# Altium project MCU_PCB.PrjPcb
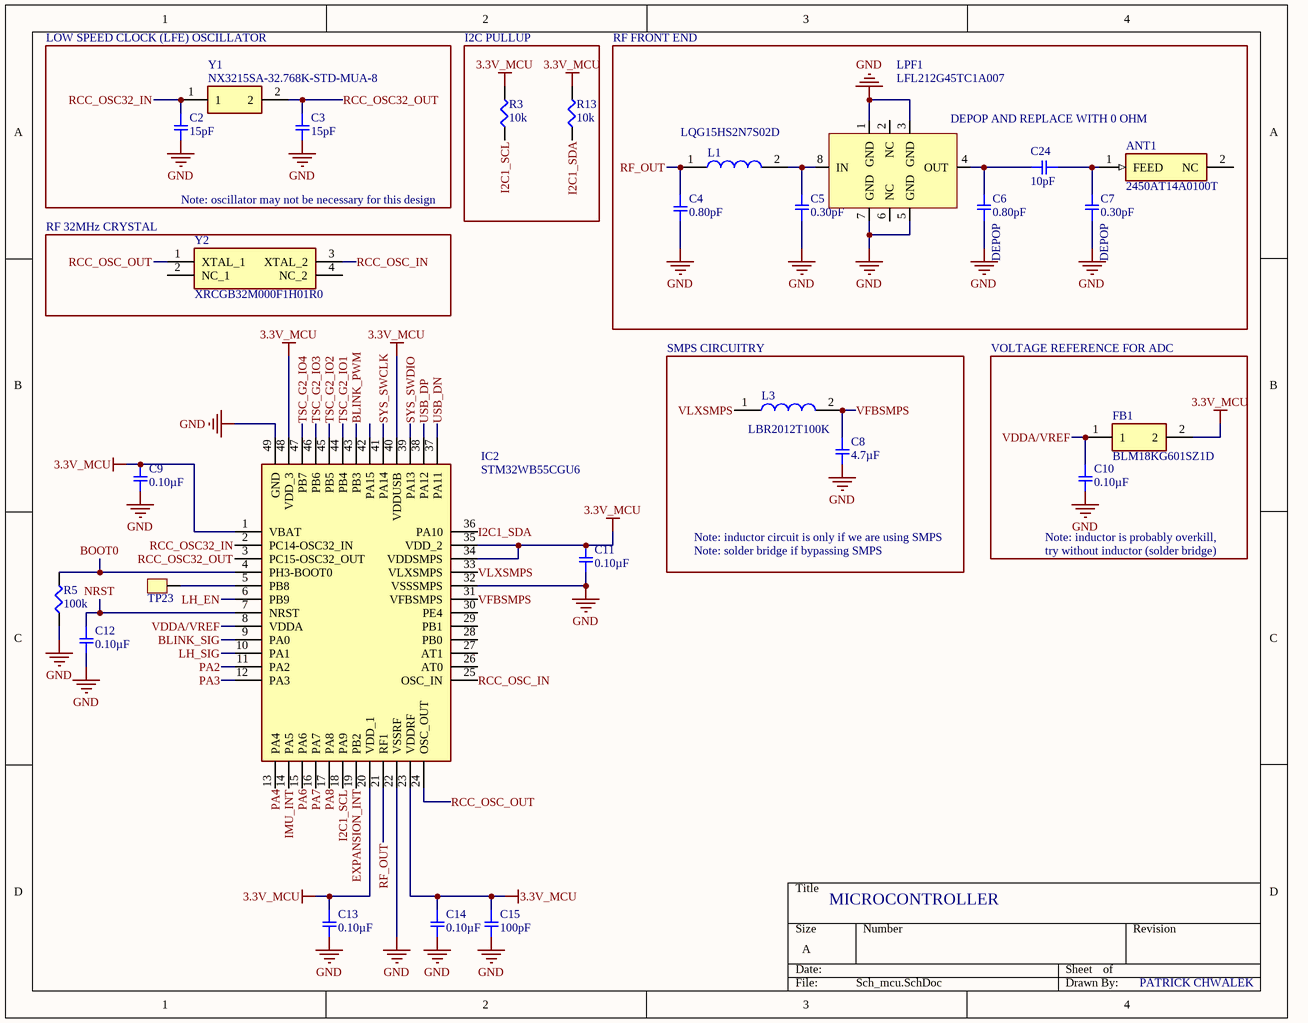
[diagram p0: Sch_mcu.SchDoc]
5 sheets, 82 parts. Net scope: global (net labels, ports and power ports of the same name join across sheets).
Board file: MCU_PCB_v2.PcbDoc
Sheets:
  Sch_mcu.SchDoc
  Sch_sensors.SchDoc
  Sch_external_connectors.SchDoc
  Sch_pwr.SchDoc
  Sch_stackup_mcu_pcb.SchDoc

## Sheet Sch_mcu.SchDoc
size A

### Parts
ANT1  2450AT14A0100T  [ANTC1608X40N]
C2  15pF  [SMD-0402C]
C3  15pF  [SMD-0402C]
C4  0.80pF  [SMD-0402C]
C5  0.30pF  [SMD-0402C]
C6  0.80pF  [SMD-0402C]
C7  0.30pF  [SMD-0402C]
C8  4.7µF  [SMD-0402C]
C9  0.10µF  [SMD-0402C]
C10  0.10µF  [SMD-0402C]
C11  0.10µF  [SMD-0402C]
C12  0.10µF  [SMD-0402C]
C13  0.10µF  [SMD-0402C]
C14  0.10µF  [SMD-0402C]
C15  100pF  [SMD-0402C]
C24  10pF  [SMD-0402C]
FB1  BLM18KG601SZ1D  [BEADC1608X95N]
IC2  STM32WB55CGU6  [QFN50P700X700X65-49N-D]
L1  LQG15HS2N7S02D  [INDC1005X55N]
L3  LBR2012T100K  [INDC2012X145N]
LPF1  LFL212G45TC1A007  [LFL212G45TC1A007]
R3  10k  [SMD-0402-RES]
R5  100k  [SMD-0402-RES]
R13  10k  [SMD-0402-RES]
TP23  TestPoint  [TestPoint_0.4mm]  (value not drawn)
Y1  NX3215SA-32.768K-STD-MUA-8  [NX3215SA]
Y2  XRCGB32M000F1H01R0  [XRCGB32M000F1H01R0]

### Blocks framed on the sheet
I2C PULLUP: R3 R13
RF 32MHz CRYSTAL: Y2

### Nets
3.3V_MCU: C9.1 C11.1 C13.1 C14.1 C15.1 FB1.2 IC2.1(VBAT) IC2.20(VDD_1) IC2.23(VDDRF) IC2.34(VDDSMPS) IC2.35(VDD_2) IC2.40(VDDUSB) IC2.48(VDD_3) R3.2 R13.2
GND: C2.2 C3.2 C4.2 C5.1 C6.1 C7.1 C8.2 C9.2 C10.2 C11.2 C12.2 C13.2 C14.2 C15.2 IC2.22(VSSRF) IC2.32(VSSSMPS) IC2.49(GND) LPF1.1(GND) LPF1.3(GND) LPF1.5(GND) LPF1.7(GND) R5.1
BLINK_PWM: IC2.43(PB3)
BLINK_SIG: IC2.9(PA0)
BOOT0: IC2.4(PH3-BOOT0) R5.2
EXPANSION_INT: IC2.19(PB2)
I2C1_SCL: IC2.18(PA9) R3.1
I2C1_SDA: IC2.36(PA10) R13.1
IMU_INT: IC2.14(PA5)
LH_EN: IC2.6(PB9)
LH_SIG: IC2.10(PA1)
NRST: C12.1 IC2.7(NRST)
PA2: IC2.11(PA2)
PA3: IC2.12(PA3)
PA4: IC2.13(PA4)
PA6: IC2.15(PA6)
PA7: IC2.16(PA7)
PA8: IC2.17(PA8)
RCC_OSC32_IN: C2.1 IC2.2(PC14-OSC32_IN) Y1.1
RCC_OSC32_OUT: C3.1 IC2.3(PC15-OSC32_OUT) Y1.2
RCC_OSC_IN: IC2.25(OSC_IN) Y2.3(XTAL_2)
RCC_OSC_OUT: IC2.24(OSC_OUT) Y2.1(XTAL_1)
RF_OUT: C4.1 IC2.21(RF1) L1.1
SYS_SWCLK: IC2.41(PA14)
SYS_SWDIO: IC2.39(PA13)
TSC_G2_IO1: IC2.44(PB4)
TSC_G2_IO2: IC2.45(PB5)
TSC_G2_IO3: IC2.46(PB6)
TSC_G2_IO4: IC2.47(PB7)
USB_DN: IC2.37(PA11)
USB_DP: IC2.38(PA12)
VDDA/VREF: C10.1 FB1.1 IC2.8(VDDA)
VFBSMPS: C8.1 IC2.31(VFBSMPS) L3.2
VLXSMPS: IC2.33(VLXSMPS) L3.1
NetANT1_1: ANT1.1(FEED) C7.2 C24.1
NetC5_2: C5.2 L1.2 LPF1.8(IN)
NetC6_2: C6.2 C24.2 LPF1.4(OUT)
NetIC2_5: IC2.5(PB8) TP23.1

Not connected (* = marked no-connect by the designer): ANT1 2(NC); IC2 26(AT0) 27(AT1) 28(PB0) 29(PB1) 30(PE4) 42(PA15); LPF1 2(NC) 6(NC); Y2 2(NC_1) 4(NC_2)

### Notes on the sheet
- LOW SPEED CLOCK (LFE) OSCILLATOR
- RF FRONT END
- (near LPF1) DEPOP AND REPLACE WITH 0 OHM
- Note: oscillator may not be necessary for this design
- (near C6) DEPOP
- (near C7) DEPOP
- SMPS CIRCUITRY
- VOLTAGE REFERENCE FOR ADC
- Note: inductor circuit is only if we are using SMPS
- Note: solder bridge if bypassing SMPS
- (near C10) Note: inductor is probably overkill,
- try without inductor (solder bridge)
- MICROCONTROLLER
- PATRICK CHWALEK

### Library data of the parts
ANT1 = 2450AT14A0100T: Antenna; Manufacturer_Name: JOHANSON TECHNOLOGY
C2 C3 = GCM1555C1H150JA16D: CAP CER 15PF 50V NP0 0402; Manufacturer: Murata Electronics North America; Factory Stock: 0; Unit Price (USD): 0.1; Minimum Quantity: 1; Tolerance: ±5%; Temperature Coefficient: C0G, NP0
C4 C6 = GRM1555C1HR80BA01D: CAP CER 0.8PF 50V NP0 0402; Manufacturer: Murata Electronics North America; Factory Stock: 0; Unit Price (USD): 0.1; Minimum Quantity: 1; Tolerance: ±0.1pF; Temperature Coefficient: C0G, NP0
C5 C7 = GRM1555C1HR30WA01D: CAP CER 0.3PF 50V NP0 0402; Manufacturer: Murata Electronics North America; Factory Stock: 0; Unit Price (USD): 0.16; Minimum Quantity: 1; Tolerance: ±0.05pF; Temperature Coefficient: C0G, NP0
C8 = GRM153R60G475ME15D: CAP CER 4.7UF 4V X5R 0402; Manufacturer: Murata Electronics North America; Factory Stock: 0; Unit Price (USD): 0.27; Minimum Quantity: 1; Tolerance: ±20%
C9-C14 = GCM155R71C104KA55D: CAP CER 0.1UF 16V X7R 0402; Manufacturer: Murata Electronics North America; Factory Stock: 0; Unit Price (USD): 0.1; Minimum Quantity: 1; Tolerance: ±10%
C15 = GCM1555C1H101JA16D: CAP CER 100PF 50V NP0 0402; Manufacturer: Murata Electronics North America; Factory Stock: 0; Unit Price (USD): 0.1; Minimum Quantity: 1; Tolerance: ±5%; Temperature Coefficient: C0G, NP0
C24 = GRM1555C1HR80BA01D: CAP CER 10PF 50V NP0 0402; Manufacturer: Murata Electronics North America; Factory Stock: 0; Unit Price (USD): 0.1; Minimum Quantity: 1; Tolerance: ±0.1pF; Temperature Coefficient: C0G, NP0
FB1 = BLM18KG601SZ1D: Ferrite Bead; Manufacturer_Name: Murata Electronics
IC2 = STM32WB55CGU6: Integrated Circuit; Manufacturer_Name: STMicroelectronics
L1 = LQG15HS2N7S02D: Inductor; Manufacturer_Name: Murata Electronics
L3 = LBR2012T100K: Inductor; Manufacturer_Name: TAIYO YUDEN
R3 R13 = ERJ-2GEJ103X: RES SMD 10K OHM 5% 1/10W 0402; Manufacturer: Panasonic Electronic Components; Factory Stock: 0; Unit Price (USD): 0.00350; @ qty: 1500; Minimum Quantity: 1; Power (Watts): 0.1W, 1/10W; Temperature Coefficient: ±200ppm/°C
R5 = ERJ-2GEJ473X: RES SMD 100K OHM 5% 1/10W 0402; Manufacturer: Panasonic Electronic Components; Factory Stock: 0; Unit Price (USD): 0.00350; @ qty: 1500; Minimum Quantity: 1; Power (Watts): 0.1W, 1/10W; Temperature Coefficient: ±200ppm/°C
Y1 = NX3215SA-32.768K-STD-MUA-8: Crystal or Oscillator; Manufacturer_Name: NDK
Y2 = XRCGB32M000F1H01R0: Crystal or Oscillator; Manufacturer_Name: Murata Electronics

## Sheet Sch_sensors.SchDoc
size A
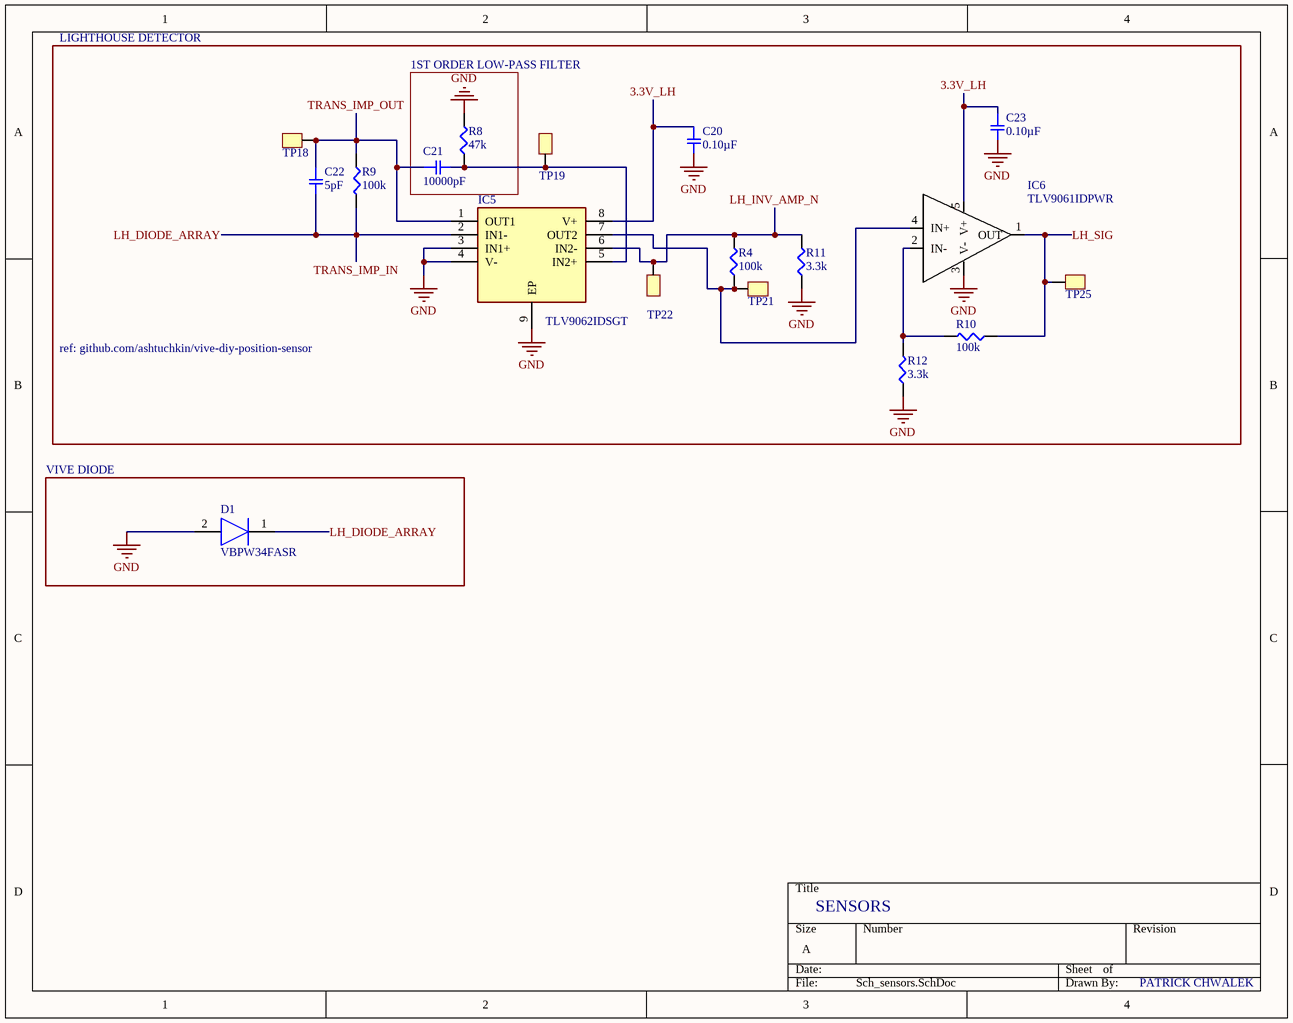
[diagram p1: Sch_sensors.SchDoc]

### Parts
C20  0.10µF  [SMD-0402C]
C21  10000pF  [SMD-0402C]
C22  5pF  [SMD-0402C]
C23  0.10µF  [SMD-0402C]
D1  VBPW34FASR  [VBPW34FASR]
IC5  TLV9062IDSGT  [SON50P200X200X80-9N]
IC6  TLV9061IDPWR  [X2SON]
R4  100k  [SMD-0402-RES]
R8  47k  [SMD-0402-RES]
R9  100k  [SMD-0402-RES]
R10  100k  [SMD-0402-RES]
R11  3.3k  [SMD-0402-RES]
R12  3.3k  [SMD-0402-RES]
TP18  TestPoint  [TestPoint_0.4mm]  (value not drawn)
TP19  TestPoint  [TestPoint_0.4mm]  (value not drawn)
TP21  TestPoint  [TestPoint_0.4mm]  (value not drawn)
TP22  TestPoint  [TestPoint_0.4mm]  (value not drawn)
TP25  TestPoint  [TestPoint_0.4mm]  (value not drawn)

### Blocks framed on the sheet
1ST ORDER LOW-PASS FILTER: C21 R8
VIVE DIODE: D1

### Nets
GND: C20.2 C23.2 D1.2(K) IC5.3(IN1+) IC5.4(V-) IC5.9(EP) IC6.3(V-) R8.2 R11.1 R12.1
3.3V_LH: C20.1 C23.1 IC5.8(V+) IC6.5(V+)
LH_DIODE_ARRAY: C22.2 D1.1(A) IC5.2(IN1-) R9.2  [also labelled TRANS_IMP_IN]
LH_INV_AMP_N: IC5.6(IN2-) R4.2 R11.2 TP22.1
LH_SIG: IC6.1(OUT) R10.1 TP25.1
TRANS_IMP_OUT: C21.1 C22.1 IC5.1(OUT1) R9.1 TP18.1
NetC21_2: C21.2 IC5.5(IN2+) R8.1 TP19.1
NetIC5_7: IC5.7(OUT2) IC6.4(IN+) R4.1 TP21.1
NetIC6_2: IC6.2(IN-) R10.2 R12.2

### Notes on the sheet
- LIGHTHOUSE DETECTOR
- ref: github.com/ashtuchkin/vive-diy-position-sensor
- SENSORS
- PATRICK CHWALEK

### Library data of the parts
C20 C23 = GCM155R71C104KA55D: as C9 on sheet Sch_mcu
C21 = GCM155R71H103KA55D: CAP CER 10000PF 50V X7R 0402; Manufacturer: Murata Electronics North America; Factory Stock: 0; Unit Price (USD): 0.1; Minimum Quantity: 1; Tolerance: ±10%
C22 = GJM1555C1H5R0BB01D: CAP CER 5PF 50V NP0 0402; Manufacturer: Murata Electronics North America; Factory Stock: 0; Unit Price (USD): 0.2; Minimum Quantity: 1; Tolerance: ±0.1pF; Temperature Coefficient: C0G, NP0
D1 = VBPW34FASR: Diode; Manufacturer_Name: Vishay
IC5 = TLV9062IDSGT: Integrated Circuit; Manufacturer_Name: Texas Instruments
IC6 = TLV9061DPWR
R4 R9 R10 = ERJ-2GEJ473X: as R5 on sheet Sch_mcu
R8 = ERJ-2GEJ473X: RES SMD 47K OHM 5% 1/10W 0402; Manufacturer: Panasonic Electronic Components; Factory Stock: 0; Unit Price (USD): 0.00350; @ qty: 1500; Minimum Quantity: 1; Power (Watts): 0.1W, 1/10W; Temperature Coefficient: ±200ppm/°C
R11 R12 = ERJ-2GEJ332X: RES SMD 3.3K OHM 5% 1/10W 0402; Manufacturer: Panasonic Electronic Components; Factory Stock: 0; Unit Price (USD): 0.00350; @ qty: 1500; Minimum Quantity: 1; Power (Watts): 0.1W, 1/10W; Temperature Coefficient: ±200ppm/°C

## Sheet Sch_external_connectors.SchDoc
size A
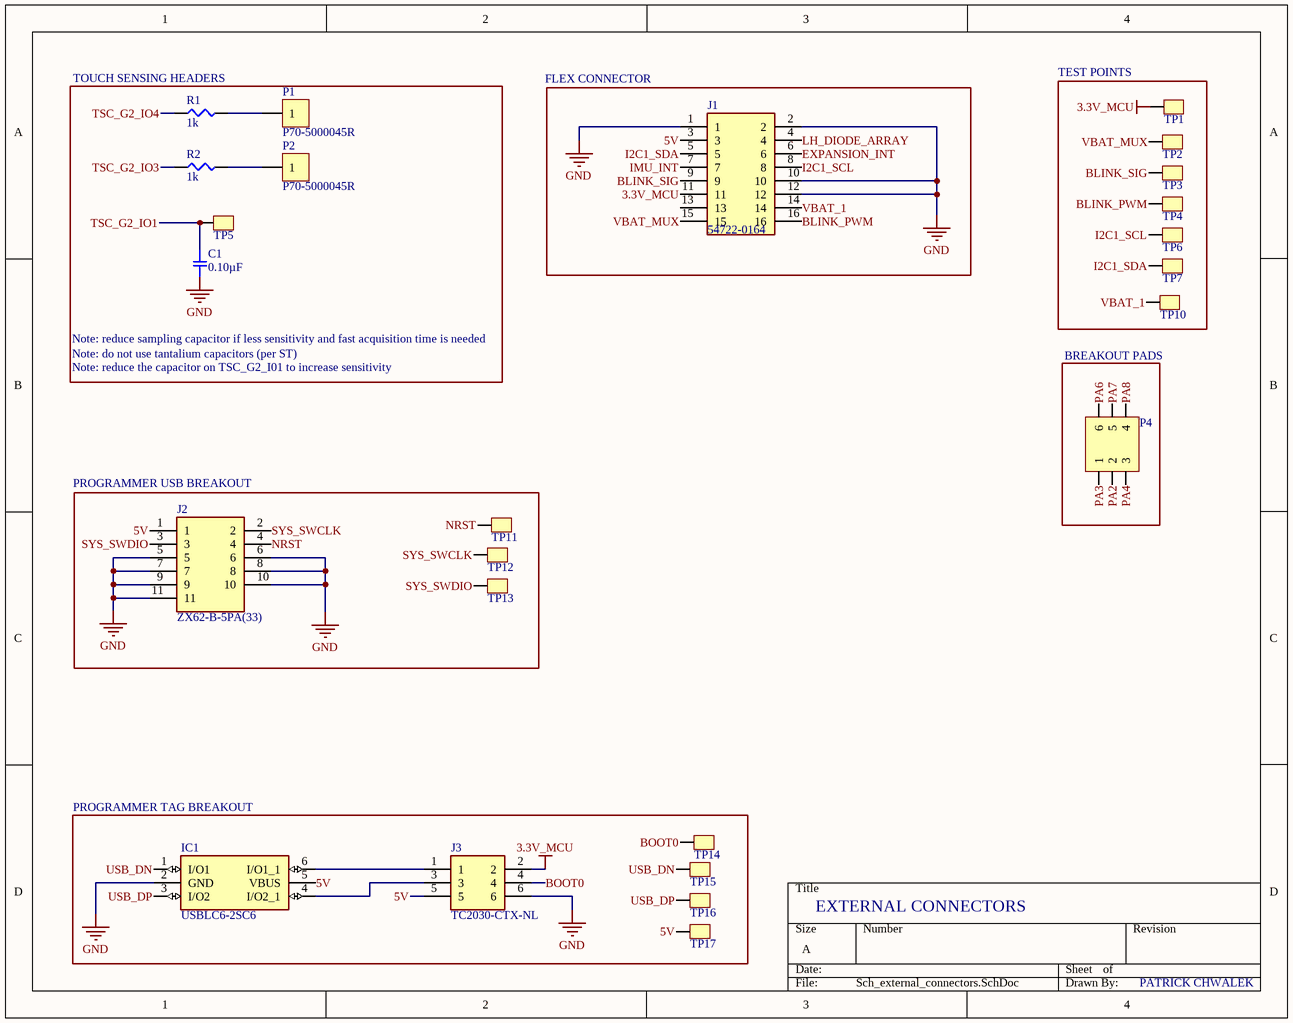
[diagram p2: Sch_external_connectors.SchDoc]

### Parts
C1  0.10µF  [SMD-0402C]
IC1  USBLC6-2SC6  [SOT95P280X145-6N]
J1  54722-0164  [54722-0164]
J2  ZX62-B-5PA(33)  [ZX62B5PA33]
J3  TC2030-CTX-NL  [TC2030MCPNL10]
P1  P70-5000045R  [P70-5000045R]
P2  P70-5000045R  [P70-5000045R]
P4  Captivates_Breakout  [CAPTIVATE_BREAKOUT_PADS]  (value not drawn)
R1  1k  [SMD-0402-RES]
R2  1k  [SMD-0402-RES]
TP1  TestPoint  [TestPoint_0.4mm]  (value not drawn)
TP2  TestPoint  [TestPoint_0.4mm]  (value not drawn)
TP3  TestPoint  [TestPoint_0.4mm]  (value not drawn)
TP4  TestPoint  [TestPoint_0.4mm]  (value not drawn)
TP5  TestPoint  [TestPoint_0.4mm]  (value not drawn)
TP6  TestPoint  [TestPoint_0.4mm]  (value not drawn)
TP7  TestPoint  [TestPoint_0.4mm]  (value not drawn)
TP10  TestPoint  [TestPoint_0.4mm]  (value not drawn)
TP11  TestPoint  [TestPoint_0.4mm]  (value not drawn)
TP12  TestPoint  [TestPoint_0.4mm]  (value not drawn)
TP13  TestPoint  [TestPoint_0.4mm]  (value not drawn)
TP14  TestPoint  [TestPoint_0.4mm]  (value not drawn)
TP15  TestPoint  [TestPoint_0.4mm]  (value not drawn)
TP16  TestPoint  [TestPoint_0.4mm]  (value not drawn)
TP17  TestPoint  [TestPoint_0.4mm]  (value not drawn)

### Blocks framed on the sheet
FLEX CONNECTOR: J1
TEST POINTS: TP1-TP4 TP6 TP7 TP10
BREAKOUT PADS: P4
PROGRAMMER USB BREAKOUT: J2 TP11-TP13
PROGRAMMER TAG BREAKOUT: IC1 J3 TP14-TP17

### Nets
3.3V_MCU: J1.11 J3.2 TP1.1
GND: C1.2 IC1.2(GND) J1.1 J1.2 J1.10 J1.12 J2.5 J2.6 J2.7 J2.8 J2.9 J2.10 J2.11 J3.6
5V: IC1.5(VBUS) J1.3 J2.1 J3.5 TP17.1
BLINK_PWM: J1.16 TP4.1
BLINK_SIG: J1.9 TP3.1
BOOT0: J3.4 TP14.1
EXPANSION_INT: J1.6
I2C1_SCL: J1.8 TP6.1
I2C1_SDA: J1.5 TP7.1
IMU_INT: J1.7
LH_DIODE_ARRAY: J1.4
NRST: J2.4 TP11.1
PA2: P4.2
PA3: P4.1
PA4: P4.3
PA6: P4.6
PA7: P4.5
PA8: P4.4
SYS_SWCLK: J2.2 TP12.1
SYS_SWDIO: J2.3 TP13.1
TSC_G2_IO1: C1.1 TP5.1
TSC_G2_IO3: R2.1
TSC_G2_IO4: R1.1
USB_DN: IC1.1(I/O1) TP15.1
USB_DP: IC1.3(I/O2) TP16.1
VBAT_1: J1.14 TP10.1
VBAT_MUX: J1.15 TP2.1
NetIC1_4: IC1.4(I/O2_1) J3.3
NetIC1_6: IC1.6(I/O1_1) J3.1
NetP1_1: P1.1 R1.2
NetP2_1: P2.1 R2.2

Not connected (* = marked no-connect by the designer): J1 13

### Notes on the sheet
- (near R1) TOUCH SENSING HEADERS
- Note: reduce sampling capacitor if less sensitivity and fast acquisition time is needed
- Note: do not use tantalium capacitors (per ST)
- Note: reduce the capacitor on TSC_G2_I01 to increase sensitivity
- EXTERNAL CONNECTORS
- PATRICK CHWALEK

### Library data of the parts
C1 = GCM155R71C104KA55D: as C9 on sheet Sch_mcu
IC1 = USBLC6-2SC6: Integrated Circuit; Manufacturer_Name: STMicroelectronics; Allied_Number: 70389689
J1 = 54722-0164: Connector; Manufacturer_Name: Molex
J2 = ZX62-B-5PA(33): Connector; Manufacturer_Name: Hirose
J3 = TC2030-CTX-NL: Connector; Manufacturer_Name: Tag Connect
R1 R2 = ERJ-2GEJ102X: RES SMD 1K OHM 5% 1/10W 0402; Manufacturer: Panasonic Electronic Components; Factory Stock: 0; Unit Price (USD): 0.00350; @ qty: 1500; Minimum Quantity: 1; Power (Watts): 0.1W, 1/10W; Temperature Coefficient: ±200ppm/°C

## Sheet Sch_pwr.SchDoc
size A
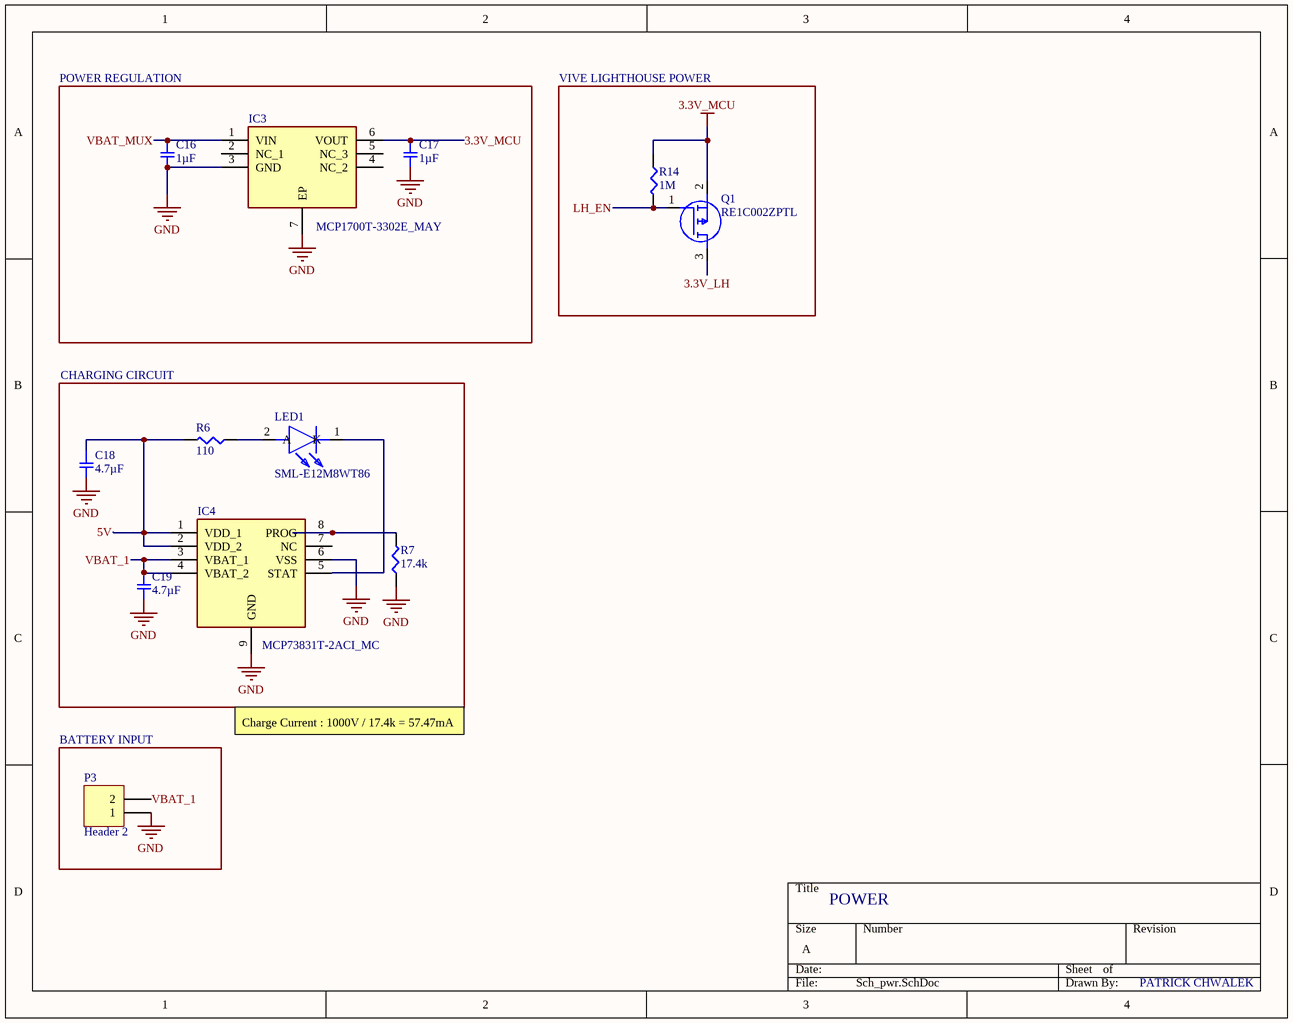
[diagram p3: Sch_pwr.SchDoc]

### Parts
C16  1µF  [SMD-0402C]
C17  1µF  [SMD-0402C]
C18  4.7µF  [SMD-0402C]
C19  4.7µF  [SMD-0402C]
IC3  MCP1700T-3302E_MAY  [SON65P200X200X90-7N]
IC4  MCP73831T-2ACI_MC  [SON50P300X200X100-9N-D]
LED1  SML-E12M8WT86  [LEDC1608X46N]
P3  Header 2  [HDR1X2]
Q1  RE1C002ZPTL  [SOTFL50P160X85-3N]
R6  110  [SMD-0402-RES]
R7  17.4k  [SMD-0402-RES]
R14  1M  [SMD-0402-RES]

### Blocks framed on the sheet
POWER REGULATION: C16 C17 IC3
VIVE LIGHTHOUSE POWER: Q1 R14
CHARGING CIRCUIT: C18 C19 IC4 LED1 R6 R7
BATTERY INPUT: P3

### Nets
3.3V_MCU: C17.1 IC3.6(VOUT) Q1.2(S) R14.1
GND: C16.2 C17.2 C18.2 C19.2 IC3.3(GND) IC3.7(EP) IC4.6(VSS) IC4.9(GND) P3.1 R7.1
3.3V_LH: Q1.3(D)
5V: C18.1 IC4.1(VDD_1) IC4.2(VDD_2) R6.2
LH_EN: Q1.1(G) R14.2
VBAT_1: C19.1 IC4.3(VBAT_1) IC4.4(VBAT_2) P3.2
VBAT_MUX: C16.1 IC3.1(VIN)
NetIC4_5: IC4.5(STAT) LED1.1(K)
NetIC4_8: IC4.8(PROG) R7.2
NetLED1_2: LED1.2(A) R6.1

Not connected (* = marked no-connect by the designer): IC3 2(NC_1) 4(NC_2) 5(NC_3); IC4 7(NC)

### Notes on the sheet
- Charge Current : 1000V / 17.4k = 57.47mA
- POWER
- PATRICK CHWALEK

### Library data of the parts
C16 C17 = GCM155C71A105KE38D: CAP CER 1UF 10V X7S 0402; Manufacturer: Murata Electronics North America; Factory Stock: 0; Unit Price (USD): 0.12; Minimum Quantity: 1; Tolerance: ±10%
C18 C19 = GRM153R60G475ME15D: as C8 on sheet Sch_mcu
IC3 = MCP1700T-3302E_MAY: Integrated Circuit; Manufacturer_Name: Microchip; Manufacturer_Part_Number: MCP1700T-3302E/MAY; Allied_Number: 70567878
IC4 = MCP73831T-2ACI_MC: Integrated Circuit; Manufacturer_Name: Microchip; Manufacturer_Part_Number: MCP73831T-2ACI/MC; Allied_Number: 70452042
LED1 = SML-E12M8WT86: LED; Manufacturer_Name: ROHM Semiconductor
P3 = Header 2: Header, 2-Pin
Q1 = RE1C002ZPTL: MOSFET (P-Channel); Manufacturer_Name: ROHM Semiconductor
R6 = ERJ-2RKF8062X: RES SMD 110 OHM 5% 1/10W 0402; Manufacturer: Panasonic Electronic Components; Factory Stock: 0; Unit Price (USD): 0.00496; @ qty: 1500; Minimum Quantity: 1; Power (Watts): 0.1W, 1/10W; Temperature Coefficient: ±100ppm/°C
R7 = ERJ-2GEJ103X: RES SMD 17.4K OHM 1% 1/10W 0402; Manufacturer: Panasonic Electronic Components; Factory Stock: 0; Unit Price (USD): 0.00350; @ qty: 1500; Minimum Quantity: 1; Power (Watts): 0.1W, 1/10W; Temperature Coefficient: ±200ppm/°C
R14 = ERJ-2GEJ105X: RES SMD 1M OHM 5% 1/10W 0402; Manufacturer: Panasonic Electronic Components; Factory Stock: 0; Unit Price (USD): 0.00350; @ qty: 1500; Minimum Quantity: 1; Power (Watts): 0.1W, 1/10W; Temperature Coefficient: ±200ppm/°C

## Sheet Sch_stackup_mcu_pcb.SchDoc
size A

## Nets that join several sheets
3.3V_MCU: Sch_mcu (15 pins), Sch_external_connectors (J1.11 J3.2 TP1.1), Sch_pwr (C17.1 IC3.6 Q1.2 R14.1)
GND: Sch_mcu (22 pins), Sch_sensors (10 pins), Sch_external_connectors (14 pins), Sch_pwr (10 pins)
3.3V_LH: Sch_sensors (C20.1 C23.1 IC5.8 IC6.5), Sch_pwr (Q1.3)
5V: Sch_external_connectors (5 pins), Sch_pwr (C18.1 IC4.1 IC4.2 R6.2)
BLINK_PWM: Sch_mcu (IC2.43), Sch_external_connectors (J1.16 TP4.1)
BLINK_SIG: Sch_mcu (IC2.9), Sch_external_connectors (J1.9 TP3.1)
BOOT0: Sch_mcu (IC2.4 R5.2), Sch_external_connectors (J3.4 TP14.1)
EXPANSION_INT: Sch_mcu (IC2.19), Sch_external_connectors (J1.6)
I2C1_SCL: Sch_mcu (IC2.18 R3.1), Sch_external_connectors (J1.8 TP6.1)
I2C1_SDA: Sch_mcu (IC2.36 R13.1), Sch_external_connectors (J1.5 TP7.1)
IMU_INT: Sch_mcu (IC2.14), Sch_external_connectors (J1.7)
LH_DIODE_ARRAY: Sch_sensors (C22.2 D1.1 IC5.2 R9.2), Sch_external_connectors (J1.4)
LH_EN: Sch_mcu (IC2.6), Sch_pwr (Q1.1 R14.2)
LH_SIG: Sch_mcu (IC2.10), Sch_sensors (IC6.1 R10.1 TP25.1)
NRST: Sch_mcu (C12.1 IC2.7), Sch_external_connectors (J2.4 TP11.1)
PA2: Sch_mcu (IC2.11), Sch_external_connectors (P4.2)
PA3: Sch_mcu (IC2.12), Sch_external_connectors (P4.1)
PA4: Sch_mcu (IC2.13), Sch_external_connectors (P4.3)
PA6: Sch_mcu (IC2.15), Sch_external_connectors (P4.6)
PA7: Sch_mcu (IC2.16), Sch_external_connectors (P4.5)
PA8: Sch_mcu (IC2.17), Sch_external_connectors (P4.4)
SYS_SWCLK: Sch_mcu (IC2.41), Sch_external_connectors (J2.2 TP12.1)
SYS_SWDIO: Sch_mcu (IC2.39), Sch_external_connectors (J2.3 TP13.1)
TSC_G2_IO1: Sch_mcu (IC2.44), Sch_external_connectors (C1.1 TP5.1)
TSC_G2_IO3: Sch_mcu (IC2.46), Sch_external_connectors (R2.1)
TSC_G2_IO4: Sch_mcu (IC2.47), Sch_external_connectors (R1.1)
USB_DN: Sch_mcu (IC2.37), Sch_external_connectors (IC1.1 TP15.1)
USB_DP: Sch_mcu (IC2.38), Sch_external_connectors (IC1.3 TP16.1)
VBAT_1: Sch_external_connectors (J1.14 TP10.1), Sch_pwr (C19.1 IC4.3 IC4.4 P3.2)
VBAT_MUX: Sch_external_connectors (J1.15 TP2.1), Sch_pwr (C16.1 IC3.1)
